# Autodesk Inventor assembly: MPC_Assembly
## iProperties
Shininess: 64.0
Length Units: 11269
Angle Units: 11279
Time Units: 11290
Mass Units: 11283
Length Display Precision: 3
Angle Display Precision: 2
Compacted: True
Created: 2004-08
Part Number: MPC_Assembly
Document SubType Name: Assembly
Designer: John Blackburn
Manufacturer: Standard
Standards Organization: Custom
Density: 0.0
Volumn: 0.0
Area: 0.0
PropertySet Name: Model Information
Control State: 0
Master: False
Checked Out: False
Author: John Blackburn
